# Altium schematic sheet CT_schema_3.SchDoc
size 461 x 327 mm
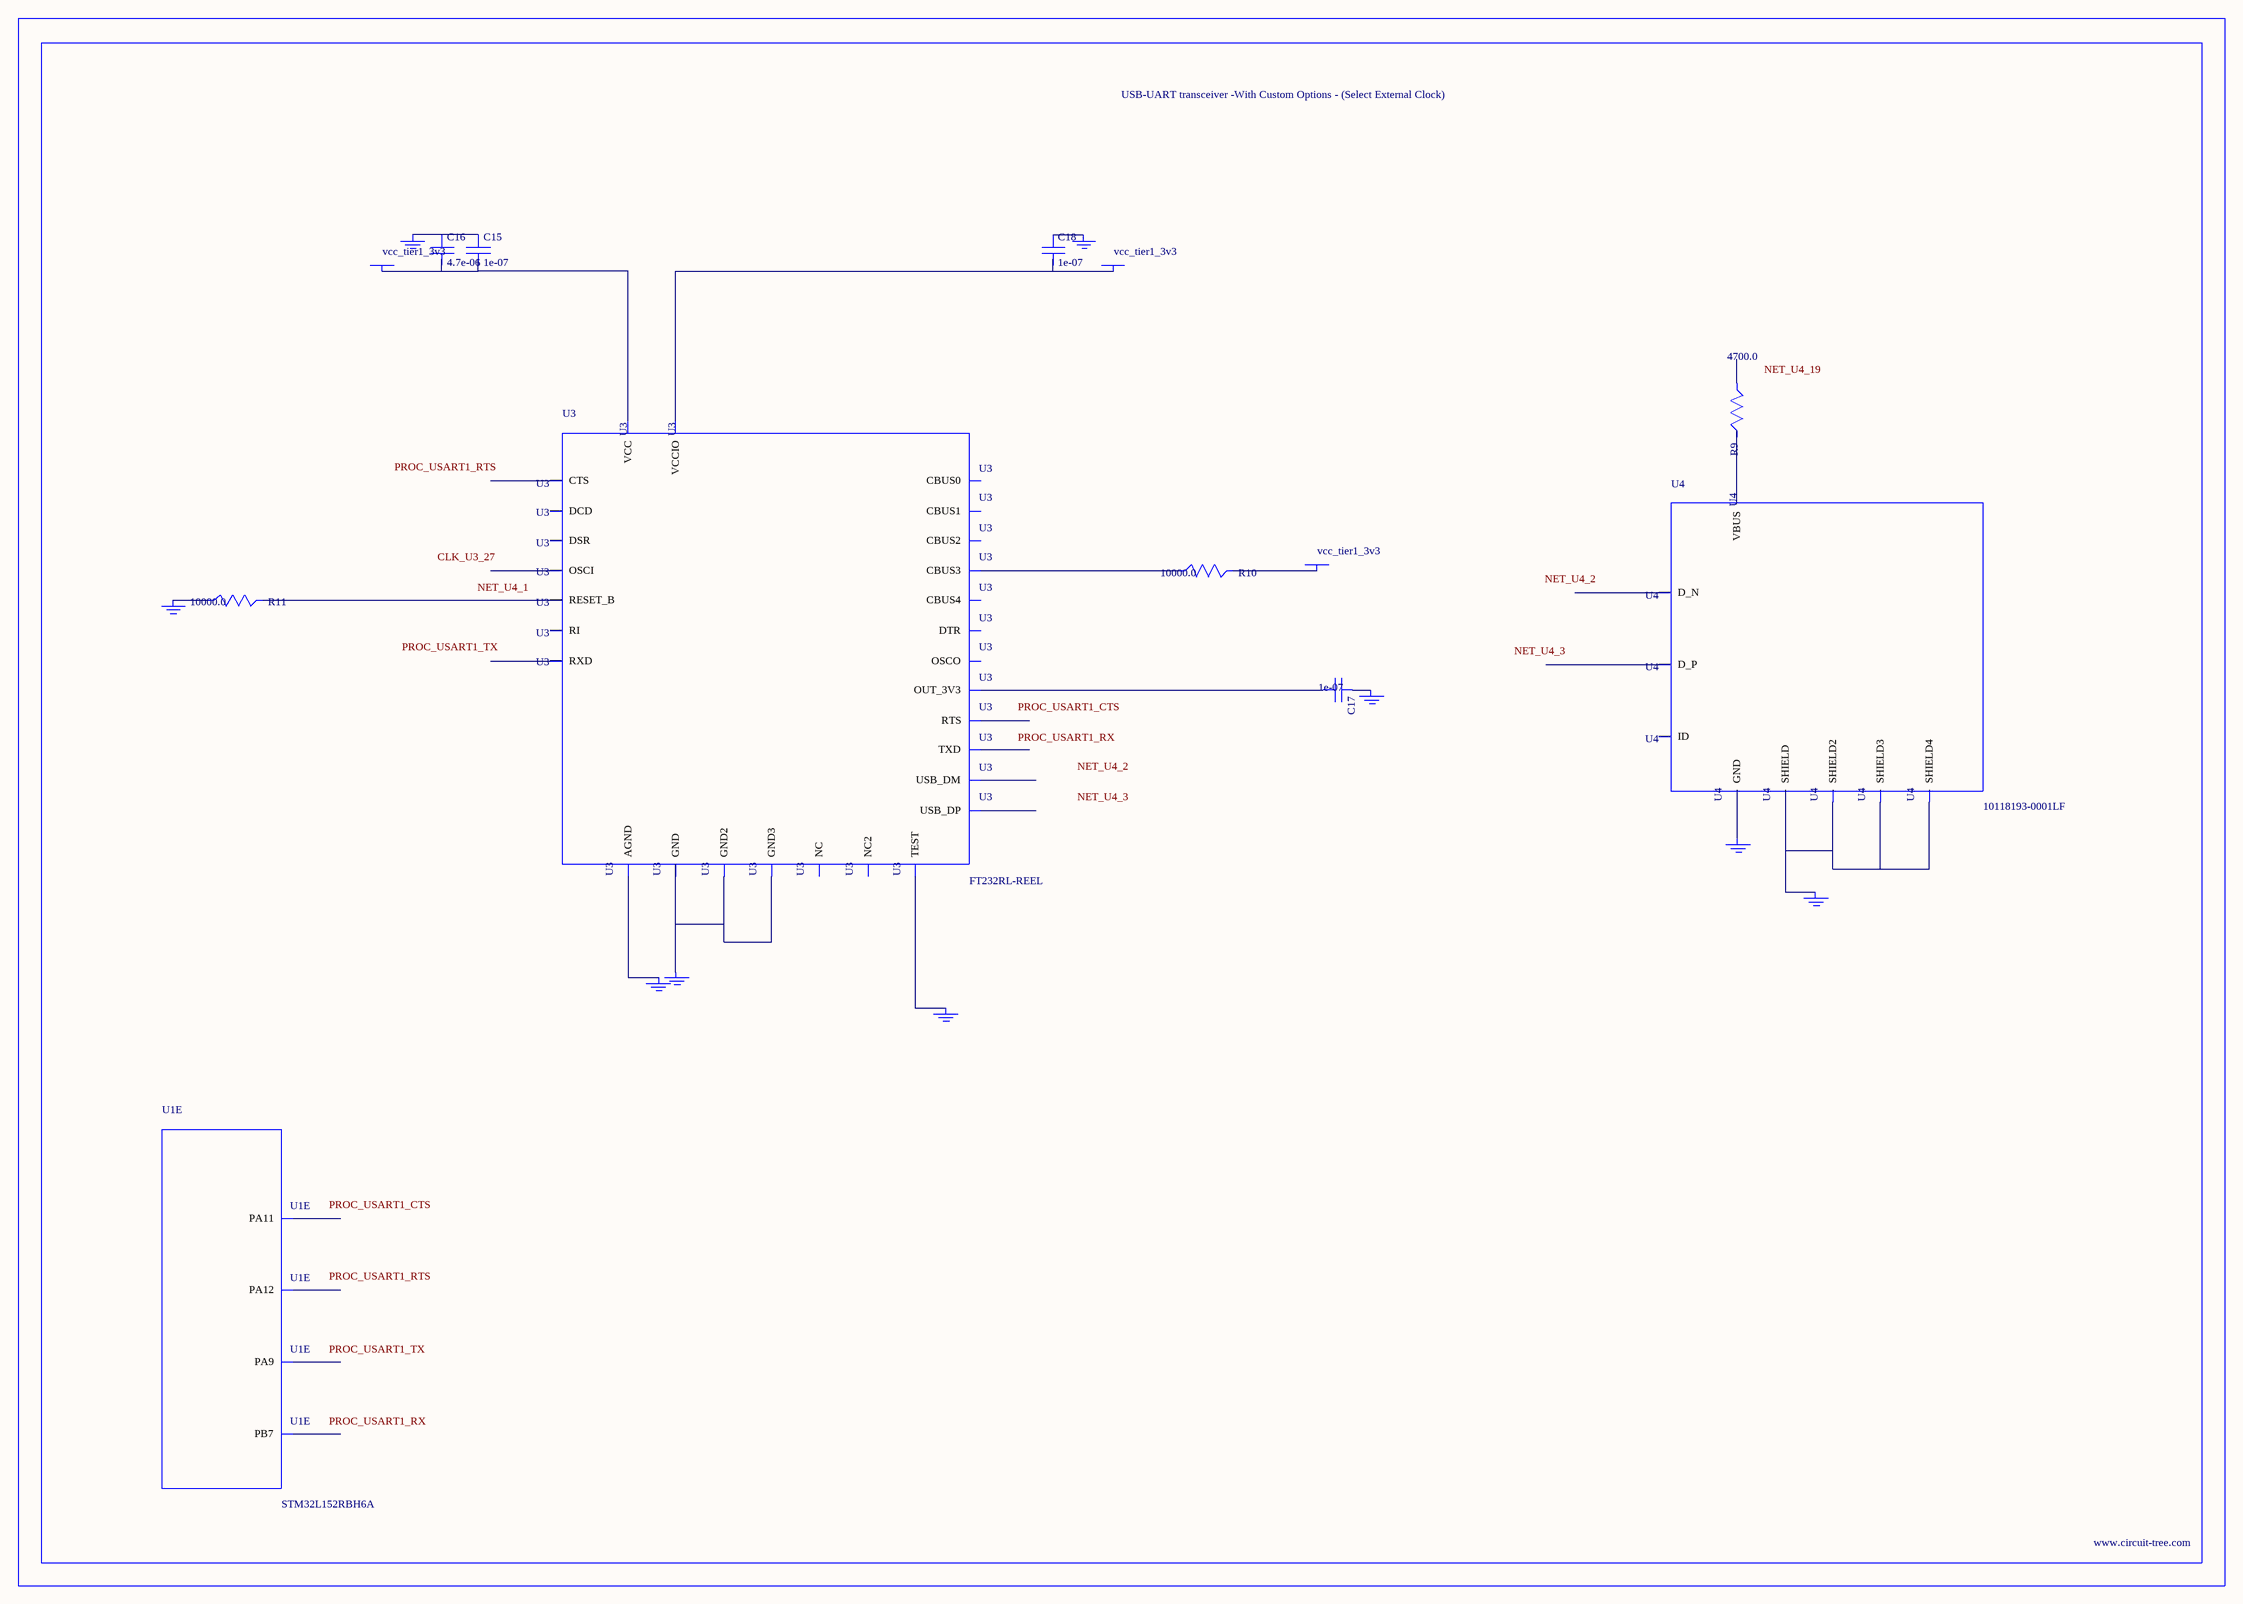
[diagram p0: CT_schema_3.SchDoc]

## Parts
BORDER2  (no value)
C15  1e-07  [C0402]
C16  4.7e-06  [C0805]
C17  1e-07  [C0402]
C18  1e-07  [C0402]
GND_INSTANCE_2_0  (no value)
GND_INSTANCE_2_1  (no value)
GND_INSTANCE_2_2  (no value)
GND_INSTANCE_2_3  (no value)
GND_INSTANCE_2_4  (no value)
GND_INSTANCE_2_5  (no value)
GND_INSTANCE_2_6  (no value)
GND_INSTANCE_2_7  (no value)
GND_INSTANCE_2_8  (no value)
POWER_INSTANCE_2_0  vcc_tier1_3v3
POWER_INSTANCE_2_1  vcc_tier1_3v3
POWER_INSTANCE_2_2  vcc_tier1_3v3
R9  4700.0  [R0603]
R10  10000.0  [R0603]
R11  10000.0  [R0603]
U1  STM32L152RBH6A  [TFBGA64]  (part E of 7)
U3  FT232RL-REEL  [SSOP-28]
U4  10118193-0001LF  [FCI_10118193-0001LF]

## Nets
NetC15_1: C15.1 C16.1 GND_INSTANCE_2_3.0(GND)
NetC15_2: C15.2 C16.2 POWER_INSTANCE_2_2.0(PWR) U3.20(VCC)
NetC17_1: C17.1 GND_INSTANCE_2_1.0(GND)
NetC17_2: C17.2 U3.17(OUT_3V3)
NetC18_1: C18.1 GND_INSTANCE_2_0.0(GND)
NetC18_2: C18.2 POWER_INSTANCE_2_0.0(PWR) U3.4(VCCIO)
NetGND_INSTANCE_2_2_0: GND_INSTANCE_2_2.0(GND) R11.1
NetGND_INSTANCE_2_4_0: GND_INSTANCE_2_4.0(GND) U3.25(AGND)
NetGND_INSTANCE_2_5_0: GND_INSTANCE_2_5.0(GND) U3.26(TEST)
NetGND_INSTANCE_2_6_0: GND_INSTANCE_2_6.0(GND) U3.7(GND) U3.18(GND2) U3.21(GND3)
NetGND_INSTANCE_2_7_0: GND_INSTANCE_2_7.0(GND) U4.6(SHIELD) U4.7(SHIELD2) U4.8(SHIELD3) U4.9(SHIELD4)
NetGND_INSTANCE_2_8_0: GND_INSTANCE_2_8.0(GND) U4.5(GND)
NetPOWER_INSTANCE_2_1_0: POWER_INSTANCE_2_1.0(PWR) R10.2
NetR9_2: R9.2 U4.1(VBUS)
NetR10_1: R10.1 U3.14(CBUS3)
NetR11_2: R11.2 U3.19(RESET_B)

Not connected (* = marked no-connect by the designer): R9 1; U1 B8(PA12) C3(PB7) C7(PA9) C8(PA11); U3 1(TXD) 2(DTR) 3(RTS) 5(RXD) 6(RI) 8(NC) 9(DSR) 10(DCD) 11(CTS) 12(CBUS4) 13(CBUS2) 15(USB_DP) 16(USB_DM) 22(CBUS1) 23(CBUS0) 24(NC2) 27(OSCI) 28(OSCO); U4 2(D_N) 3(D_P) 4(ID)

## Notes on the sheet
- Labels drawn without touching a wire or pin: CLK_U3_27, NET_U4_1, NET_U4_2, NET_U4_3, NET_U4_19, PROC_USART1_CTS, PROC_USART1_RTS, PROC_USART1_RX, PROC_USART1_TX

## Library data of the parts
BORDER2 = BORDER_PAGE2
C15 C17 C18 = C0402C104K3RACTU
C16 = C0805C475K4RACTU
GND_INSTANCE_2_0-GND_INSTANCE_2_8 = GND
POWER_INSTANCE_2_0-POWER_INSTANCE_2_2 = PWR
R9 = RC0603JR-074K7L
R10 R11 = RC0603JR-0710KL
